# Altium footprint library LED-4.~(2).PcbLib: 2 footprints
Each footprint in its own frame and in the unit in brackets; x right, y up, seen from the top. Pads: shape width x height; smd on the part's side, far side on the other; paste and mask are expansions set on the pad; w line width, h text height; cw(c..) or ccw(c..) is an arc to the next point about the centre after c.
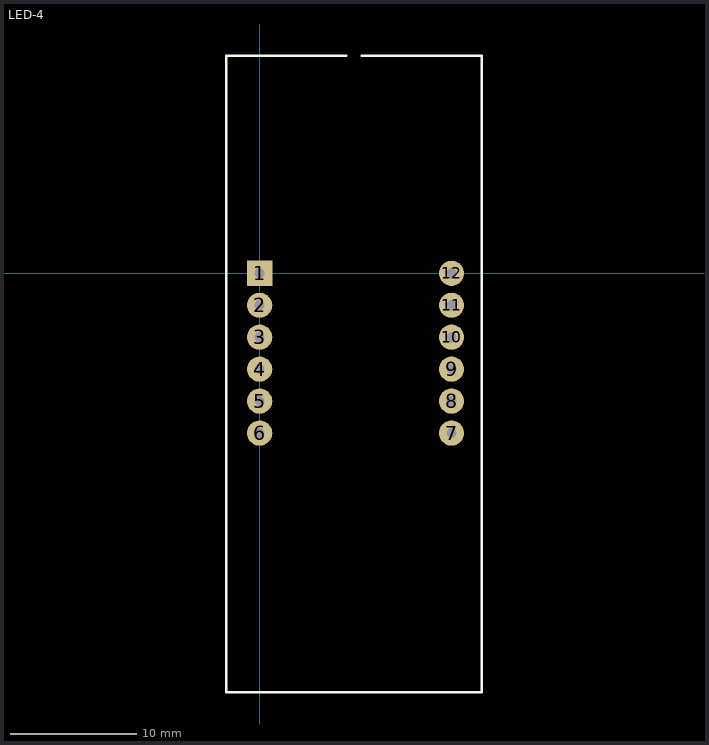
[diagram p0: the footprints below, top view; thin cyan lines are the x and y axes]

## LED-4 [mm]
pads (12):
  rect 2x2 / inner round 1.524 / far side round 1.524 hole 0.8: 1(0,0)
  round 2 / inner round 1.524 / far side round 1.524 hole 0.8: 2(0,-2.54) 3(0,-5.08) 4(0,-7.62) 5(0,-10.16) 6(0,-12.7) 7(15.24,-12.7) 8(15.24,-10.16) 9(15.24,-7.62) 10(15.24,-5.08) 11(15.24,-2.54) 12(15.24,0)
Top Overlay:
  lines w0.2: 6.858,17.272 -2.667,17.272 -2.667,-33.274 17.653,-33.274 17.653,17.272 8.128,17.272

## LED-4 - duplicate [mm]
